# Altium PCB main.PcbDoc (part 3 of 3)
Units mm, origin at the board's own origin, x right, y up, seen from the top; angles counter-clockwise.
Board outline 326.29 x 232.51 mm, 2 copper layers (TopLayer, BottomLayer); 87 components, 134 nets, 466 pads, 108 vias.
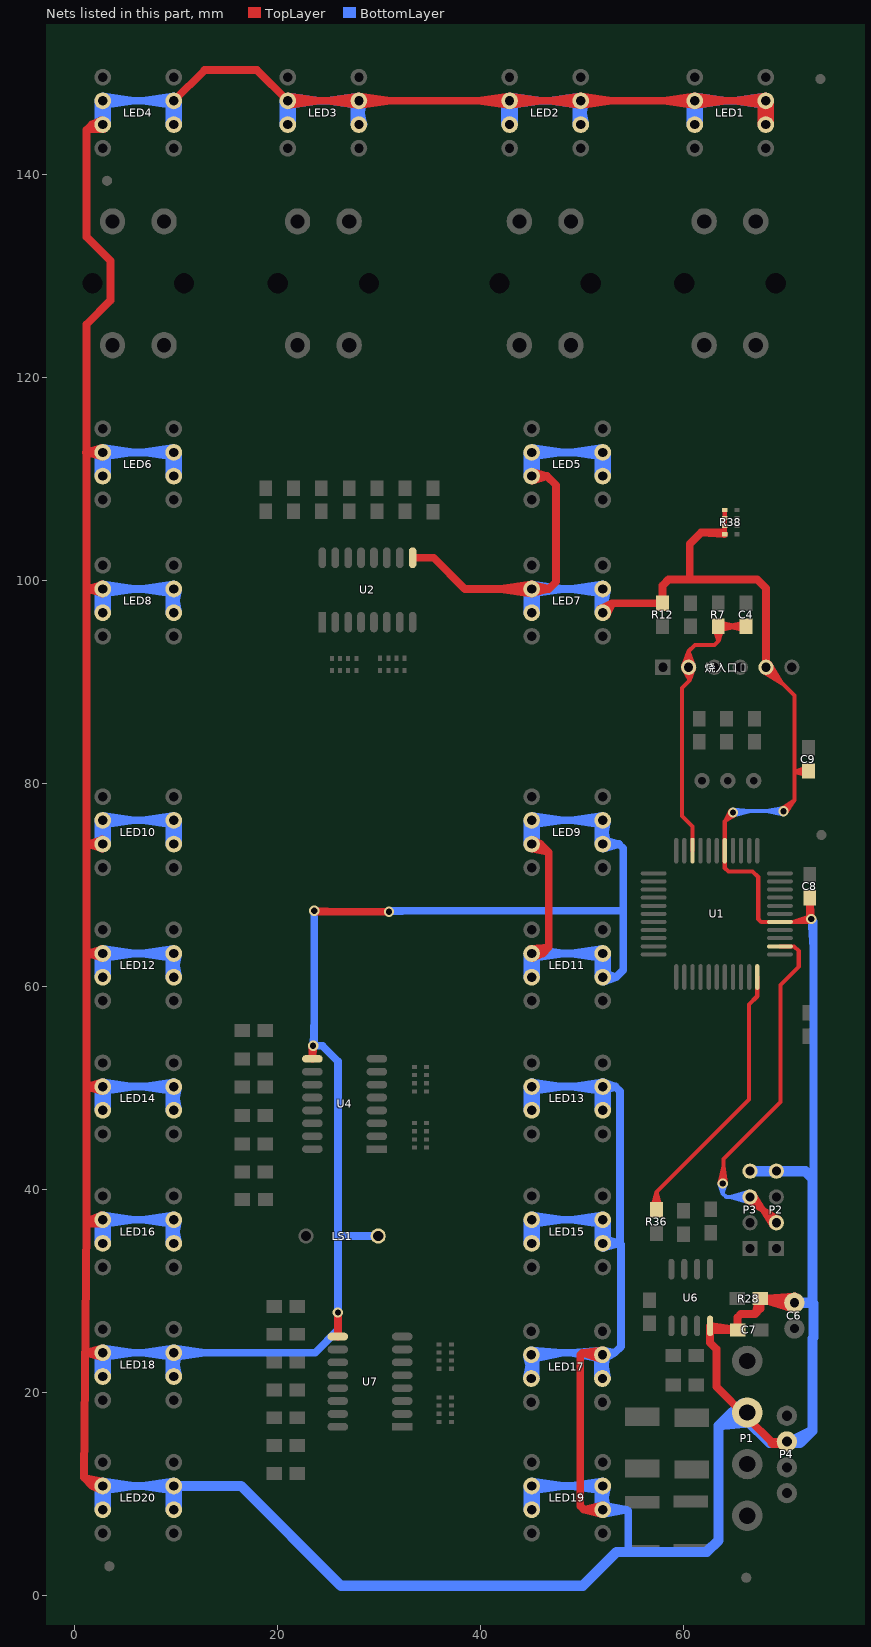
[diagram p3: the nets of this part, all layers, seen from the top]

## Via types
v1: diameter 1.016, hole 0.61, TopLayer to BottomLayer, tented both sides, 108 vias

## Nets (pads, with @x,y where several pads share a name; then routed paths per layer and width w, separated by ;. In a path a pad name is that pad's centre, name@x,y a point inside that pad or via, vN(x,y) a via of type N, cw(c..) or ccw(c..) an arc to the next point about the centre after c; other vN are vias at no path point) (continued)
TX: P2.2 P3.3 U1.35 | length 61.7
  TopLayer w0.406: v1@63.553,40.629 63.93,42.319 ; v1@64.16,40.603 63.93,42.319 ; P3.3@66.211,38.838 68.16,37.656 P3.3@66.978,39.606 ; P3.3@66.548,39.268 69.088,36.728 P2.2@69.139,36.728 67.508,38.308 ; P2.2@68.714,36.384 67.508,38.308 ; P2.2@69.469,37.164 67.508,38.308 ; U1.35@69.497,63.95 70.89,63.95 ; 63.93,42.319 v1(63.856,40.589) 63.93,40.515 63.93,43.004 69.545,48.619 69.545,60.151 71.351,61.957 71.351,63.488 70.89,63.95 ; 70.89,63.95 70.564,63.95 70.89,63.95
  BottomLayer w0.406: v1@63.555,40.541 63.856,39.624 ; v1@64.157,40.541 63.856,39.624 ; P3.3@66.472,38.727 64.579,39.268 ; P3.3@66.472,39.81 64.579,39.268 ; 63.856,39.624 v1(63.856,40.589) 63.856,39.624 ; 63.856,39.624 64.211,39.268 P3.3@66.548,39.268 64.579,39.268
TX2: R36.2 U1.33 | length 32.8
  TopLayer w0.406: R36.2@56.917,38.177 57.345,39.76 ; R36.2@57.345,37.993 57.345,39.76 ; R36.2@57.345,38.12 57.345,39.76 ; R36.2@57.773,38.177 57.345,39.76 ; U1.33@67.262,59.86 67.262,59.036 ; U1.33@67.262,60.927 67.262,59.036 ; 57.345,39.76 66.449,48.864 66.449,58.224 67.262,59.036
VCC: C6.1 C7.1 C8.1 C9.1 LED1.A LED2.A LED3.A LED4.A LED5.A LED6.A LED7.A LED8.A LED9.A LED10.A LED11.A LED12.A LED13.A LED14.A LED15.A LED16.A LED17.A LED18.A LED19.A LED20.A LS1.1 P1.2 P2.4 P3.4 P4.2 R12.2 R28.1 R38.1 R38.2 R38.3 R38.4 U1.5 U1.38 U2.9 U4.9 U6.8 U7.9 烧入口1.5 | length 2560.3
  TopLayer w0.406: U1.5@64.062,72.306 64.062,71.676 ; U1.5@64.062,74.44 64.062,75.862 ; v1@64.628,77.316 64.062,76.254 ; v1@65.073,76.907 64.062,76.254 ; 烧入口1.5@67.785,91.01 69.735,89.828 烧入口1.5@68.553,91.777 ; 烧入口1.5@68.123,91.44 70.917,88.646 70.917,81.125 ; U1.38@68.43,66.363 67.648,66.363 ; v1@69.652,77.498 70.917,78.334 ; v1(69.845,77.262) 70.917,78.334 ; v1@70.081,77.069 70.917,78.334 ; U1.38@70.564,66.363 71.986,66.363 ; C9.1@72.195,81.641 70.917,81.125 ; C9.1@72.254,80.79 70.917,81.125 ; v1@72.396,66.881 71.986,66.363 ; v1@72.512,66.938 70.817,66.363 ; v1@72.515,66.938 U1.38@70.76,66.363 ; v1@72.606,66.338 U1.38@70.76,66.363 ; v1@72.607,66.338 70.817,66.363 ; v1@72.647,66.343 71.986,66.363 ; R38.3@64.059,105.334 R38.2@64.059,106.134 ; R38.3@64.059,105.334 R38.4@64.059,104.534 R38.3@64.059,105.334 ; R38.3@64.059,105.334 R38.2@64.059,106.134 ; R38.2@64.059,106.134 R38.1@64.059,106.934 R38.2@64.059,106.134 ; 64.062,71.676 U1.5@64.062,73.373 64.062,76.254 ; 64.062,71.676 64.414,71.323 66.802,71.323 67.361,70.764 67.361,66.65 67.648,66.363 ; 64.062,76.254 64.922,77.114 64.897,77.14 v1(64.876,77.14) 64.062,76.254 ; 67.648,66.363 U1.38@69.497,66.363 72.306,66.363 v1(72.585,66.642) ; U1.38@70.76,66.363 v1(72.585,66.642) ; 70.817,66.363 v1(72.585,66.642) ; 70.917,78.334 70.917,81.125 ; 70.917,81.125 72.197,81.125 C9.1@72.292,81.22 70.917,81.125 ; 71.986,66.363 v1(72.585,66.642)
  TopLayer w0.762: 1.151,112.597 1.212,112.597 ; 1.174,50.137 1.212,50.137 ; 1.174,63.247 1.212,63.247 ; LED14.A@2.505,50.137 1.212,50.137 ; LED12.A@2.505,63.247 1.212,63.247 ; LED20.A@2.573,10.424 0.965,11.633 ; LED4.A@2.606,145.284 1.212,144.366 ; LED16.A@2.631,37.438 1.212,36.619 ; LED10.A@2.703,74.023 1.372,74.023 ; LED6.A@2.703,112.597 1.212,112.597 ; LED10.A@2.73,73.584 1.372,74.023 ; LED10.A@2.73,74.462 1.372,74.023 ; LED8.A@2.736,98.707 1.248,99.147 ; LED8.A@2.736,99.587 1.248,99.147 ; LED14.A@2.737,49.697 1.212,50.137 ; LED14.A@2.737,50.577 1.212,50.137 ; LED12.A@2.737,62.807 1.212,63.247 ; LED12.A@2.737,63.687 1.212,63.247 ; LED6.A@2.737,112.157 1.212,112.597 ; LED6.A@2.737,113.037 1.212,112.597 ; LED18.A@2.74,23.476 1.128,23.917 ; LED18.A@2.74,24.357 1.128,23.917 ; LED14.A@2.799,50.137 1.212,50.137 ; LED12.A@2.799,63.247 1.212,63.247 ; LED10.A@2.799,74.023 1.372,74.023 ; LED6.A@2.799,112.597 1.212,112.597 ; LED16.A@2.85,36.585 1.212,36.619 ; LED4.A@2.879,144.446 1.212,144.366 ; LED20.A@2.936,11.23 0.965,11.633 ; LED4.A@9.799,147.217 12.833,150.25 17.996,150.25 LED3.A@21.029,147.217 LED3.A@28.029,147.217 ; LED3.A@21.061,146.773 24.141,147.217 LED3.A@21.061,147.66 ; 26.427,67.361 v1(23.622,67.462) 23.724,67.361 v1(30.988,67.361) 28.194,67.361 ; LED3.A@27.997,146.773 24.918,147.217 ; LED3.A@27.997,147.66 24.918,147.217 ; LED3.A@28.061,146.773 31.141,147.217 LED3.A@28.061,147.66 ; U2.9@33.319,102.225 35.392,102.225 38.471,99.147 LED7.A@45.039,99.147 ; LED2.A@42.837,146.773 39.758,147.217 ; LED2.A@42.837,147.66 39.758,147.217 ; LED2.A@42.901,146.773 45.981,147.217 LED2.A@42.901,147.66 ; LED9.A@44.894,73.603 46.736,73.203 ; LED11.A@44.942,63.68 46.736,63.856 ; LED7.A@45.007,98.703 41.928,99.147 ; LED7.A@45.007,99.59 41.928,99.147 ; LED5.A@45.039,110.263 46.556,110.263 ; LED7.A@45.098,98.706 46.721,99.147 ; LED7.A@45.098,99.587 46.721,99.147 ; LED5.A@45.104,109.824 46.556,110.263 ; LED5.A@45.104,110.703 46.556,110.263 ; LED11.A@45.24,62.85 46.736,63.856 ; LED9.A@45.279,74.398 46.736,73.203 ; LED2.A@49.837,146.773 46.758,147.217 ; LED2.A@49.837,147.66 46.758,147.217 ; LED2.A@49.901,146.773 52.981,147.217 LED2.A@49.901,147.66 ; LED7.A@51.782,97.176 52.979,97.753 ; LED17.A@51.922,23.287 50.028,23.917 ; LED19.A@51.985,8.032 50.201,8.473 ; LED19.A@51.985,8.915 50.201,8.473 ; LED17.A@52.008,24.166 50.028,23.917 ; LED17.A@52.014,23.722 50.028,23.917 ; LED19.A@52.039,8.473 50.201,8.473 ; LED17.A@52.039,23.917 50.028,23.917 ; LED7.A@52.039,96.813 52.979,97.753 ; LED7.A@52.402,96.556 52.979,97.753 ; 55.015,97.753 R12.2@57.936,97.753 ; R12.2@57.936,97.88 57.936,99.491 ; LED1.A@61.067,146.773 57.988,147.217 LED1.A@61.067,147.66 ; LED1.A@61.131,146.773 64.211,147.217 LED1.A@61.131,147.66 ; U6.8@62.611,25.857 62.611,24.919 ; R28.1@67.442,29.253 67.056,27.737 ; LED1.A@67.657,147.174 LED1.A@68.099,144.883 ; LED1.A@67.657,147.259 LED1.A@67.657,144.926 ; LED1.A@67.673,147.091 LED1.A@68.542,144.926 ; LED1.A@68.067,146.773 64.988,147.217 LED1.A@68.067,147.66 ; 烧入口1.5@68.123,91.44 68.123,99.212 67.259,100.076 60.604,100.076 ; LED1.A@68.526,147.091 LED1.A@67.657,144.926 ; LED1.A@68.542,147.174 LED1.A@68.099,144.883 ; LED1.A@68.542,147.259 LED1.A@68.542,144.926 ; 68.775,15.037 66.275,17.537 63.246,20.566 63.246,24.284 62.611,24.919 ; C6.1@70.783,28.25 R28.1@67.696,29.253 ; C6.1@70.787,28.249 R28.1@67.569,29.253 ; 0.965,11.633 1.792,10.807 ; 0.965,11.633 1.212,36.619 ; 0.965,11.633 LED20.A@2.799,10.807 ; 1.128,23.917 LED18.A@2.799,23.917 1.128,23.917 ; 1.212,36.619 1.619,37.027 ; 1.212,36.619 1.212,50.137 ; 1.212,36.619 LED16.A@2.799,37.027 ; 1.212,50.137 1.212,63.247 ; 1.212,63.247 1.212,112.597 ; 1.212,112.597 1.212,125.214 3.561,127.564 3.561,131.465 1.212,133.815 1.212,144.366 ; 1.212,144.366 1.729,144.883 ; 1.212,144.366 LED4.A@2.799,144.883 ; 1.248,99.147 LED8.A@2.799,99.147 1.248,99.147 ; 1.619,37.027 LED16.A@2.799,37.027 ; 1.619,37.027 2.715,36.59 1.619,37.027 ; 1.619,37.027 2.715,37.463 1.619,37.027 ; 1.619,37.027 LED16.A@2.799,37.027 ; 1.619,37.027 LED16.A@2.799,37.027 ; 1.729,144.883 LED4.A@2.799,144.883 ; 1.729,144.883 2.707,144.449 1.729,144.883 ; 1.729,144.883 2.707,145.318 1.729,144.883 ; 1.729,144.883 LED4.A@2.799,144.883 ; 1.729,144.883 LED4.A@2.799,144.883 ; 1.792,10.807 LED20.A@2.799,10.807 ; 1.792,10.807 2.701,10.373 1.792,10.807 ; 1.792,10.807 2.701,11.24 1.792,10.807 ; 1.792,10.807 LED20.A@2.799,10.807 ; 1.792,10.807 LED20.A@2.799,10.807 ; 24.918,147.217 LED3.A@28.029,147.217 ; v1(25.959,27.889) 25.959,25.53 v1(25.959,27.889) ; v1(25.959,27.889) U7.9@25.949,25.52 v1(25.959,27.889) ; LED3.A@28.029,147.217 LED2.A@42.869,147.217 ; 39.758,147.217 LED2.A@42.869,147.217 ; 41.928,99.147 LED7.A@45.039,99.147 ; LED2.A@42.869,147.217 LED2.A@49.869,147.217 ; LED11.A@45.039,63.247 46.127,63.247 ; LED11.A@45.039,63.247 46.736,63.856 ; LED11.A@45.039,63.247 46.127,63.247 ; LED9.A@45.039,74.023 45.915,74.023 ; LED9.A@45.039,74.023 46.736,73.203 ; LED9.A@45.039,74.023 45.915,74.023 ; LED7.A@45.039,99.147 46.721,99.147 ; 45.915,74.023 46.736,73.203 ; 45.915,74.023 45.152,74.453 45.915,74.023 ; 45.915,74.023 45.152,73.593 45.915,74.023 ; 46.127,63.247 46.736,63.856 ; 46.127,63.247 45.13,63.682 46.127,63.247 ; 46.127,63.247 45.13,62.812 46.127,63.247 ; 46.556,110.263 47.447,109.372 47.447,99.873 46.721,99.147 ; 46.736,63.856 46.736,73.203 ; 46.758,147.217 LED2.A@49.869,147.217 ; LED2.A@49.869,147.217 LED1.A@61.099,147.217 LED1.A@68.099,147.217 ; 50.028,23.917 49.835,23.724 49.835,8.839 50.201,8.473 ; 52.979,97.753 R12.2@57.936,97.753 ; R12.2@57.936,97.753 57.936,99.491 ; 57.936,99.491 58.522,100.076 60.604,100.076 ; 60.604,100.076 60.604,103.581 61.722,104.699 ; 61.722,104.699 63.754,104.699 64.009,104.534 61.722,104.699 ; 62.611,24.919 U6.8@62.611,26.568 ; U6.8@62.611,26.568 63.01,26.17 ; U6.8@62.611,26.568 C7.1@65.324,26.17 ; U6.8@62.611,26.568 63.01,26.17 ; U6.8@62.611,26.568 65.197,26.17 63.01,26.17 ; U6.8@62.611,26.568 63.01,26.17 ; 63.01,26.17 C7.1@65.324,26.17 ; C7.1@65.324,26.17 65.324,27.427 65.634,27.737 67.056,27.737 ; 67.056,27.737 67.569,28.25 ; 67.569,28.25 R28.1@67.569,29.253 ; 67.569,28.25 R28.1@67.569,29.253 ; 67.569,28.25 R28.1@67.569,29.253 ; R28.1@67.569,29.253 C6.1@70.518,29.253 ; R28.1@67.569,29.253 70.933,29.473 R28.1@67.696,29.253 ; R28.1@67.569,29.253 C6.1@70.917,28.854 ; LED1.A@67.657,144.926 LED1.A@68.099,147.217 ; R28.1@67.696,29.253 C6.1@70.518,29.253 ; R28.1@67.696,29.253 C6.1@70.917,28.854 ; LED1.A@68.099,144.883 LED1.A@68.099,147.217 ; LED1.A@68.099,147.217 LED1.A@68.542,144.926 ; C6.1@70.518,29.253 C6.1@70.917,28.854 ; v1@72.433,66.794 C8.1@72.433,68.727 v1(72.585,66.642) ; v1@72.433,66.794 v1(72.585,66.642) ; v1@72.433,66.794 72.433,68.6 v1(72.585,66.642) ; U4.9@23.449,52.87 23.449,54.082 v1(23.52,54.153) U4.9@23.449,52.87
  TopLayer w1.016: P1.2@66.275,17.537 P1.2@66.275,18.04 ; 68.775,15.037 70.256,15.037 68.775,15.037
  BottomLayer w0.406: v1@64.882,77.445 66.615,77.262 ; v1@64.924,76.839 66.615,77.262 ; v1@69.818,76.958 68.118,77.262 ; v1@69.818,77.566 68.118,77.262 ; 66.615,77.262 v1(64.876,77.14) 64.876,77.262 v1(69.845,77.262) 68.118,77.262
  BottomLayer w0.762: LED20.A@2.357,10.764 LED20.A@2.799,8.473 ; LED20.A@2.357,10.849 LED20.A@2.357,8.516 ; LED18.A@2.357,23.874 LED18.A@2.799,21.583 ; LED18.A@2.357,23.959 LED18.A@2.357,21.626 ; LED16.A@2.357,36.984 LED16.A@2.799,34.693 ; LED16.A@2.357,37.069 LED16.A@2.357,34.736 ; LED14.A@2.357,50.094 LED14.A@2.799,47.803 ; LED14.A@2.357,50.179 LED14.A@2.357,47.846 ; LED12.A@2.357,63.204 LED12.A@2.799,60.913 ; LED12.A@2.357,63.289 LED12.A@2.357,60.956 ; LED10.A@2.357,76.314 LED10.A@2.799,74.023 ; LED10.A@2.357,76.399 LED10.A@2.357,74.066 ; LED8.A@2.357,99.104 LED8.A@2.799,96.813 ; LED8.A@2.357,99.189 LED8.A@2.357,96.856 ; LED6.A@2.357,112.554 LED6.A@2.799,110.263 ; LED6.A@2.357,112.639 LED6.A@2.357,110.306 ; LED4.A@2.357,147.174 LED4.A@2.799,144.883 ; LED4.A@2.357,147.259 LED4.A@2.357,144.926 ; LED20.A@2.373,10.681 LED20.A@3.242,8.516 ; LED18.A@2.373,23.791 LED18.A@3.242,21.626 ; LED16.A@2.373,36.901 LED16.A@3.242,34.736 ; LED14.A@2.373,50.011 LED14.A@3.242,47.846 ; LED12.A@2.373,63.121 LED12.A@3.242,60.956 ; LED10.A@2.373,76.231 LED10.A@3.242,74.066 ; LED8.A@2.373,99.021 LED8.A@3.242,96.856 ; LED6.A@2.373,112.471 LED6.A@3.242,110.306 ; LED4.A@2.373,147.091 LED4.A@3.242,144.926 ; LED20.A@2.601,10.807 LED20.A@2.799,10.807 ; LED18.A@2.601,23.917 LED18.A@2.799,23.917 ; LED16.A@2.601,37.027 LED16.A@2.799,37.027 ; LED14.A@2.601,50.137 LED14.A@2.799,50.137 ; LED12.A@2.601,63.247 LED12.A@2.799,63.247 ; LED10.A@2.601,76.357 LED10.A@2.799,76.357 ; LED8.A@2.601,99.147 LED8.A@2.799,99.147 ; LED6.A@2.601,112.597 LED6.A@2.799,112.597 ; LED4.A@2.601,147.217 LED4.A@2.799,147.217 ; LED20.A@2.831,10.363 5.911,10.807 LED20.A@2.831,11.25 ; LED18.A@2.831,23.473 5.911,23.917 LED18.A@2.831,24.36 ; LED16.A@2.831,36.583 5.911,37.027 LED16.A@2.831,37.47 ; LED14.A@2.831,49.693 5.911,50.137 LED14.A@2.831,50.58 ; LED12.A@2.831,62.803 5.911,63.247 LED12.A@2.831,63.69 ; LED10.A@2.831,75.913 5.911,76.357 LED10.A@2.831,76.8 ; LED8.A@2.831,98.703 5.911,99.147 LED8.A@2.831,99.59 ; LED6.A@2.831,112.153 5.911,112.597 LED6.A@2.831,113.04 ; LED4.A@2.831,146.773 5.911,147.217 LED4.A@2.831,147.66 ; LED20.A@3.226,10.681 LED20.A@2.357,8.516 ; LED18.A@3.226,23.791 LED18.A@2.357,21.626 ; LED16.A@3.226,36.901 LED16.A@2.357,34.736 ; LED14.A@3.226,50.011 LED14.A@2.357,47.846 ; LED12.A@3.226,63.121 LED12.A@2.357,60.956 ; LED10.A@3.226,76.231 LED10.A@2.357,74.066 ; LED8.A@3.226,99.021 LED8.A@2.357,96.856 ; LED6.A@3.226,112.471 LED6.A@2.357,110.306 ; LED4.A@3.226,147.091 LED4.A@2.357,144.926 ; LED20.A@3.242,10.764 LED20.A@2.799,8.473 ; LED20.A@3.242,10.849 LED20.A@3.242,8.516 ; LED18.A@3.242,23.874 LED18.A@2.799,21.583 ; LED18.A@3.242,23.959 LED18.A@3.242,21.626 ; LED16.A@3.242,36.984 LED16.A@2.799,34.693 ; LED16.A@3.242,37.069 LED16.A@3.242,34.736 ; LED14.A@3.242,50.094 LED14.A@2.799,47.803 ; LED14.A@3.242,50.179 LED14.A@3.242,47.846 ; LED12.A@3.242,63.204 LED12.A@2.799,60.913 ; LED12.A@3.242,63.289 LED12.A@3.242,60.956 ; LED10.A@3.242,76.314 LED10.A@2.799,74.023 ; LED10.A@3.242,76.399 LED10.A@3.242,74.066 ; LED8.A@3.242,99.104 LED8.A@2.799,96.813 ; LED8.A@3.242,99.189 LED8.A@3.242,96.856 ; LED6.A@3.242,112.554 LED6.A@2.799,110.263 ; LED6.A@3.242,112.639 LED6.A@3.242,110.306 ; LED4.A@3.242,147.174 LED4.A@2.799,144.883 ; LED4.A@3.242,147.259 LED4.A@3.242,144.926 ; LED20.A@9.357,8.431 LED20.A@9.357,10.764 ; LED18.A@9.357,21.541 LED18.A@9.357,23.874 ; LED16.A@9.357,34.651 LED16.A@9.357,36.984 ; LED14.A@9.357,47.761 LED14.A@9.357,50.094 ; LED12.A@9.357,60.871 LED12.A@9.357,63.204 ; LED10.A@9.357,73.981 LED10.A@9.357,76.314 ; LED8.A@9.357,96.771 LED8.A@9.357,99.104 ; LED6.A@9.357,110.221 LED6.A@9.357,112.554 ; LED4.A@9.357,144.841 LED4.A@9.357,147.174 ; LED20.A@9.373,8.599 LED20.A@10.242,10.764 ; LED10.A@9.373,74.149 LED10.A@10.242,76.314 ; LED6.A@9.373,110.389 LED6.A@10.242,112.554 ; LED4.A@9.373,145.009 LED4.A@10.242,147.174 ; LED20.A@9.601,10.807 LED20.A@2.799,10.807 ; LED18.A@9.601,23.917 LED18.A@2.799,23.917 ; LED16.A@9.601,37.027 LED16.A@2.799,37.027 ; LED14.A@9.601,50.137 LED14.A@2.799,50.137 ; LED12.A@9.601,63.247 LED12.A@2.799,63.247 ; LED10.A@9.601,76.357 LED10.A@2.799,76.357 ; LED8.A@9.601,99.147 LED8.A@2.799,99.147 ; LED6.A@9.601,112.597 LED6.A@2.799,112.597 ; LED4.A@9.601,147.217 LED4.A@2.799,147.217 ; LED20.A@9.767,10.363 6.688,10.807 ; LED20.A@9.767,11.25 6.688,10.807 ; LED18.A@9.767,23.473 6.688,23.917 ; LED18.A@9.767,24.36 6.688,23.917 ; LED16.A@9.767,36.583 6.688,37.027 ; LED16.A@9.767,37.47 6.688,37.027 ; LED14.A@9.767,49.693 6.688,50.137 ; LED14.A@9.767,50.58 6.688,50.137 ; LED12.A@9.767,62.803 6.688,63.247 ; LED12.A@9.767,63.69 6.688,63.247 ; LED10.A@9.767,75.913 6.688,76.357 ; LED10.A@9.767,76.8 6.688,76.357 ; LED8.A@9.767,98.703 6.688,99.147 ; LED8.A@9.767,99.59 6.688,99.147 ; LED6.A@9.767,112.153 6.688,112.597 ; LED6.A@9.767,113.04 6.688,112.597 ; LED4.A@9.767,146.773 6.688,147.217 ; LED4.A@9.767,147.66 6.688,147.217 ; LED18.A@9.831,23.473 12.911,23.917 LED18.A@9.831,24.36 ; LED20.A@10.226,8.599 LED20.A@9.357,10.764 ; LED18.A@10.226,21.709 LED18.A@9.357,23.874 ; LED16.A@10.226,34.819 LED16.A@9.357,36.984 ; LED14.A@10.226,47.929 LED14.A@9.357,50.094 ; LED12.A@10.226,61.039 LED12.A@9.357,63.204 ; LED10.A@10.226,74.149 LED10.A@9.357,76.314 ; LED8.A@10.226,96.939 LED8.A@9.357,99.104 ; LED6.A@10.226,110.389 LED6.A@9.357,112.554 ; LED4.A@10.226,145.009 LED4.A@9.357,147.174 ; LED20.A@10.242,8.431 LED20.A@10.242,10.764 ; LED18.A@10.242,23.874 LED18.A@9.799,21.583 ; LED16.A@10.242,36.984 LED16.A@9.799,34.693 ; LED14.A@10.242,50.094 LED14.A@9.799,47.803 ; LED12.A@10.242,63.204 LED12.A@9.799,60.913 ; LED10.A@10.242,73.981 LED10.A@10.242,76.314 ; LED8.A@10.242,99.104 LED8.A@9.799,96.813 ; LED6.A@10.242,110.221 LED6.A@10.242,112.554 ; LED4.A@10.242,144.841 LED4.A@10.242,147.174 ; LED3.A@20.587,144.841 LED3.A@20.587,147.174 ; LED3.A@20.603,145.009 LED3.A@21.472,147.174 ; LED3.A@20.831,147.217 LED3.A@21.029,147.217 ; LED3.A@21.061,146.773 24.141,147.217 LED3.A@21.061,147.66 ; LED3.A@21.456,145.009 LED3.A@20.587,147.174 ; LED3.A@21.472,144.841 LED3.A@21.472,147.174 ; 23.622,56.958 v1(23.52,54.153) ; 23.622,64.668 v1(23.622,67.462) 23.622,54.254 v1(23.52,54.153) ; LED3.A@27.587,147.174 LED3.A@28.029,144.883 ; LED3.A@27.587,147.259 LED3.A@27.587,144.926 ; LED3.A@27.831,147.217 LED3.A@21.029,147.217 ; LED3.A@27.997,146.773 24.918,147.217 ; LED3.A@27.997,147.66 24.918,147.217 ; LED3.A@28.456,147.091 LED3.A@27.587,144.926 ; LED3.A@28.472,144.926 LED3.A@28.029,147.217 ; LED3.A@28.472,147.174 LED3.A@28.029,144.883 ; LS1.1@29.928,35.416 25.959,35.416 ; 33.794,67.462 v1(30.988,67.361) 31.09,67.462 54.051,67.462 ; LED2.A@42.427,147.174 LED2.A@42.869,144.883 ; LED2.A@42.427,147.259 LED2.A@42.427,144.926 ; LED2.A@42.443,147.091 LED2.A@43.312,144.926 ; LED2.A@42.671,147.217 LED2.A@42.869,147.217 ; LED2.A@42.901,146.773 45.981,147.217 LED2.A@42.901,147.66 ; LED2.A@43.296,147.091 LED2.A@42.427,144.926 ; LED2.A@43.312,147.174 LED2.A@42.869,144.883 ; LED2.A@43.312,147.259 LED2.A@43.312,144.926 ; LED17.A@44.572,23.67 LED17.A@45.039,21.583 ; LED17.A@44.588,21.514 LED17.A@45.457,23.681 ; LED19.A@44.597,8.431 LED19.A@44.597,10.764 ; LED15.A@44.597,34.651 LED15.A@44.597,36.984 ; LED13.A@44.597,47.761 LED13.A@44.597,50.094 ; LED11.A@44.597,60.871 LED11.A@44.597,63.204 ; LED9.A@44.597,73.981 LED9.A@44.597,76.314 ; LED7.A@44.597,96.771 LED7.A@44.597,99.104 ; LED5.A@44.597,110.221 LED5.A@44.597,112.554 ; LED19.A@44.613,8.599 LED19.A@45.482,10.764 ; LED15.A@44.613,34.819 LED15.A@45.482,36.984 ; LED13.A@44.613,47.929 LED13.A@45.482,50.094 ; LED11.A@44.613,61.039 LED11.A@45.482,63.204 ; LED9.A@44.613,74.149 LED9.A@45.482,76.314 ; LED7.A@44.613,96.939 LED7.A@45.482,99.104 ; LED5.A@44.613,110.389 LED5.A@45.482,112.554 ; LED19.A@44.841,10.807 LED19.A@45.039,10.807 ; LED17.A@44.841,23.917 LED17.A@45.039,23.917 ; LED15.A@44.841,37.027 LED15.A@45.039,37.027 ; LED13.A@44.841,50.137 LED13.A@45.039,50.137 ; LED11.A@44.841,63.247 LED11.A@45.039,63.247 ; LED9.A@44.841,76.357 LED9.A@45.039,76.357 ; LED7.A@44.841,99.147 LED7.A@45.039,99.147 ; LED5.A@44.841,112.597 LED5.A@45.039,112.597 ; LED17.A@45.018,24.166 48.144,23.917 ; LED19.A@45.071,10.363 48.151,10.807 LED19.A@45.071,11.25 ; LED15.A@45.071,36.583 48.151,37.027 LED15.A@45.071,37.47 ; LED13.A@45.071,49.693 48.151,50.137 LED13.A@45.071,50.58 ; LED11.A@45.071,62.803 48.151,63.247 LED11.A@45.071,63.69 ; LED9.A@45.071,75.913 48.151,76.357 LED9.A@45.071,76.8 ; LED7.A@45.071,98.703 48.151,99.147 LED7.A@45.071,99.59 ; LED5.A@45.071,112.153 48.151,112.597 LED5.A@45.071,113.04 ; LED17.A@45.073,23.281 48.144,23.917 ; LED17.A@45.456,21.346 LED17.A@45.457,23.681 ; LED17.A@45.456,21.431 LED17.A@45.014,23.722 ; LED17.A@45.457,21.423 LED17.A@45.039,23.917 ; LED19.A@45.466,8.599 LED19.A@44.597,10.764 ; LED15.A@45.466,34.819 LED15.A@44.597,36.984 ; LED13.A@45.466,47.929 LED13.A@44.597,50.094 ; LED11.A@45.466,61.039 LED11.A@44.597,63.204 ; LED9.A@45.466,74.149 LED9.A@44.597,76.314 ; LED7.A@45.466,96.939 LED7.A@44.597,99.104 ; LED5.A@45.466,110.389 LED5.A@44.597,112.554 ; LED19.A@45.482,8.431 LED19.A@45.482,10.764 ; LED15.A@45.482,34.651 LED15.A@45.482,36.984 ; LED13.A@45.482,47.761 LED13.A@45.482,50.094 ; LED11.A@45.482,60.871 LED11.A@45.482,63.204 ; LED9.A@45.482,73.981 LED9.A@45.482,76.314 ; LED7.A@45.482,96.771 LED7.A@45.482,99.104 ; LED5.A@45.482,110.221 LED5.A@45.482,112.554 ; LED2.A@49.427,144.841 LED2.A@49.427,147.174 ; LED2.A@49.671,147.217 LED2.A@42.869,147.217 ; LED2.A@49.837,146.773 46.758,147.217 ; LED2.A@49.837,147.66 46.758,147.217 ; LED2.A@50.296,145.009 LED2.A@49.427,147.174 ; LED2.A@50.312,147.174 LED2.A@49.869,144.883 ; LED17.A@51.572,23.68 LED17.A@52.014,21.389 ; LED17.A@51.572,23.764 LED17.A@51.572,21.432 ; LED17.A@51.573,23.67 LED17.A@52.039,21.583 ; LED19.A@51.597,10.764 LED19.A@52.039,8.473 ; LED19.A@51.597,10.849 LED19.A@51.597,8.516 ; LED15.A@51.597,36.984 LED15.A@52.039,34.693 ; LED15.A@51.597,37.069 LED15.A@51.597,34.736 ; LED13.A@51.597,50.094 LED13.A@52.039,47.803 ; LED13.A@51.597,50.179 LED13.A@51.597,47.846 ; LED11.A@51.597,63.204 LED11.A@52.039,60.913 ; LED11.A@51.597,63.289 LED11.A@51.597,60.956 ; LED9.A@51.597,76.314 LED9.A@52.039,74.023 ; LED9.A@51.597,76.399 LED9.A@51.597,74.066 ; LED7.A@51.597,99.104 LED7.A@52.039,96.813 ; LED7.A@51.597,99.189 LED7.A@51.597,96.856 ; LED5.A@51.597,112.554 LED5.A@52.039,110.263 ; LED5.A@51.597,112.639 LED5.A@51.597,110.306 ; LED15.A@51.613,36.901 LED15.A@52.482,34.736 ; LED13.A@51.613,50.011 LED13.A@52.482,47.846 ; LED11.A@51.613,63.121 LED11.A@52.482,60.956 ; LED5.A@51.613,112.471 LED5.A@52.482,110.306 ; LED19.A@51.841,10.807 LED19.A@45.039,10.807 ; LED17.A@51.841,23.917 LED17.A@45.039,23.917 ; LED15.A@51.841,37.027 LED15.A@45.039,37.027 ; LED13.A@51.841,50.137 LED13.A@45.039,50.137 ; LED11.A@51.841,63.247 LED11.A@45.039,63.247 ; LED9.A@51.841,76.357 LED9.A@45.039,76.357 ; LED7.A@51.841,99.147 LED7.A@45.039,99.147 ; LED5.A@51.841,112.597 LED5.A@45.039,112.597 ; LED17.A@51.955,23.281 48.88,23.917 ; LED19.A@52.007,10.363 48.928,10.807 ; LED19.A@52.007,11.25 48.928,10.807 ; LED15.A@52.007,36.583 48.928,37.027 ; LED15.A@52.007,37.47 48.928,37.027 ; LED13.A@52.007,49.693 48.928,50.137 ; LED13.A@52.007,50.58 48.928,50.137 ; LED11.A@52.007,62.803 48.928,63.247 ; LED11.A@52.007,63.69 48.928,63.247 ; LED9.A@52.007,75.913 48.928,76.357 ; LED9.A@52.007,76.8 48.928,76.357 ; LED7.A@52.007,98.703 48.928,99.147 ; LED7.A@52.007,99.59 48.928,99.147 ; LED5.A@52.007,112.153 48.928,112.597 ; LED5.A@52.007,113.04 48.928,112.597 ; LED17.A@52.01,24.166 48.88,23.917 ; LED17.A@52.024,24.166 53.228,23.917 ; LED19.A@52.081,8.031 54.417,8.473 ; LED19.A@52.081,8.916 54.417,8.473 ; LED15.A@52.097,34.253 53.745,34.693 ; LED15.A@52.097,35.134 53.745,34.693 ; LED9.A@52.101,73.583 53.637,74.023 ; LED9.A@52.101,74.464 53.637,74.023 ; LED11.A@52.115,60.475 53.344,60.913 ; LED11.A@52.115,61.351 53.344,60.913 ; LED13.A@52.118,49.699 53.292,50.137 ; LED13.A@52.118,50.574 53.292,50.137 ; LED17.A@52.163,23.303 53.228,23.917 ; LED17.A@52.44,23.596 LED17.A@51.572,21.432 ; LED17.A@52.456,23.68 LED17.A@52.014,21.389 ; LED17.A@52.457,23.681 LED17.A@52.039,21.583 ; LED17.A@52.457,21.423 LED17.A@52.039,23.917 ; LED19.A@52.466,10.681 LED19.A@51.597,8.516 ; LED15.A@52.466,36.901 LED15.A@51.597,34.736 ; LED13.A@52.466,50.011 LED13.A@51.597,47.846 ; LED11.A@52.466,63.121 LED11.A@51.597,60.956 ; LED9.A@52.466,76.231 LED9.A@51.597,74.066 ; LED7.A@52.466,99.021 LED7.A@51.597,96.856 ; LED5.A@52.466,112.471 LED5.A@51.597,110.306 ; LED19.A@52.482,8.516 LED19.A@52.039,10.807 ; LED19.A@52.482,10.764 LED19.A@52.039,8.473 ; LED15.A@52.482,36.984 LED15.A@52.039,34.693 ; LED15.A@52.482,37.069 LED15.A@52.482,34.736 ; LED13.A@52.482,50.094 LED13.A@52.039,47.803 ; LED13.A@52.482,50.179 LED13.A@52.482,47.846 ; LED11.A@52.482,63.204 LED11.A@52.039,60.913 ; LED11.A@52.482,63.289 LED11.A@52.482,60.956 ; LED9.A@52.482,74.066 LED9.A@52.039,76.357 ; LED9.A@52.482,76.314 LED9.A@52.039,74.023 ; LED7.A@52.482,96.856 LED7.A@52.039,99.147 ; LED7.A@52.482,99.104 LED7.A@52.039,96.813 ; LED5.A@52.482,112.554 LED5.A@52.039,110.263 ; LED5.A@52.482,112.639 LED5.A@52.482,110.306 ; 54.559,4.275 54.559,4.31 54.559,8.331 54.417,8.473 ; LED1.A@60.657,144.841 LED1.A@60.657,147.174 ; LED1.A@60.673,145.009 LED1.A@61.542,147.174 ; LED1.A@60.901,147.217 LED1.A@61.099,147.217 ; LED1.A@61.131,146.773 64.211,147.217 LED1.A@61.131,147.66 ; LED1.A@61.526,145.009 LED1.A@60.657,147.174 ; LED1.A@61.542,144.841 LED1.A@61.542,147.174 ; LED1.A@67.901,147.217 LED1.A@61.099,147.217 ; LED1.A@68.067,146.773 64.988,147.217 ; LED1.A@68.067,147.66 64.988,147.217 ; LED1.A@68.099,147.217 64.988,147.217 ; 72.806,40.377 72.806,66.421 v1(72.585,66.642) 72.806,63.776 ; LED20.A@2.357,8.516 LED20.A@2.799,10.807 ; LED20.A@2.357,8.516 LED20.A@2.799,10.807 ; LED18.A@2.357,21.626 LED18.A@2.799,23.917 ; LED18.A@2.357,21.626 LED18.A@2.799,23.917 ; LED16.A@2.357,34.736 LED16.A@2.799,37.027 ; LED16.A@2.357,34.736 LED16.A@2.799,37.027 ; LED14.A@2.357,47.846 LED14.A@2.799,50.137 ; LED14.A@2.357,47.846 LED14.A@2.799,50.137 ; LED12.A@2.357,60.956 LED12.A@2.799,63.247 ; LED12.A@2.357,60.956 LED12.A@2.799,63.247 ; LED10.A@2.357,74.066 LED10.A@2.799,76.357 ; LED10.A@2.357,74.066 LED10.A@2.799,76.357 ; LED8.A@2.357,96.856 LED8.A@2.799,99.147 ; LED8.A@2.357,96.856 LED8.A@2.799,99.147 ; LED6.A@2.357,110.306 LED6.A@2.799,112.597 ; LED6.A@2.357,110.306 LED6.A@2.799,112.597 ; LED4.A@2.357,144.926 LED4.A@2.799,147.217 ; LED4.A@2.357,144.926 LED4.A@2.799,147.217 ; LED20.A@2.799,8.473 LED20.A@2.799,10.807 ; LED20.A@2.799,8.473 LED20.A@2.799,10.807 ; LED20.A@2.799,10.807 LED20.A@3.242,8.516 ; LED18.A@2.799,21.583 LED18.A@2.799,23.917 ; LED18.A@2.799,21.583 LED18.A@2.799,23.917 ; LED18.A@2.799,23.917 LED18.A@3.242,21.626 ; LED16.A@2.799,34.693 LED16.A@2.799,37.027 ; LED16.A@2.799,34.693 LED16.A@2.799,37.027 ; LED16.A@2.799,37.027 LED16.A@3.242,34.736 ; LED14.A@2.799,47.803 LED14.A@2.799,50.137 ; LED14.A@2.799,47.803 LED14.A@2.799,50.137 ; LED14.A@2.799,50.137 LED14.A@3.242,47.846 ; LED12.A@2.799,60.913 LED12.A@2.799,63.247 ; LED12.A@2.799,60.913 LED12.A@2.799,63.247 ; LED12.A@2.799,63.247 LED12.A@3.242,60.956 ; LED10.A@2.799,74.023 LED10.A@2.799,76.357 ; LED10.A@2.799,74.023 LED10.A@2.799,76.357 ; LED10.A@2.799,76.357 LED10.A@3.242,74.066 ; LED8.A@2.799,96.813 LED8.A@2.799,99.147 ; LED8.A@2.799,96.813 LED8.A@2.799,99.147 ; LED8.A@2.799,99.147 LED8.A@3.242,96.856 ; LED6.A@2.799,110.263 LED6.A@2.799,112.597 ; LED6.A@2.799,110.263 LED6.A@2.799,112.597 ; LED6.A@2.799,112.597 LED6.A@3.242,110.306 ; LED4.A@2.799,144.883 LED4.A@2.799,147.217 ; LED4.A@2.799,144.883 LED4.A@2.799,147.217 ; LED4.A@2.799,147.217 LED4.A@3.242,144.926 ; 6.688,10.807 LED20.A@9.799,10.807 ; 6.688,23.917 LED18.A@9.799,23.917 ; 6.688,37.027 LED16.A@9.799,37.027 ; 6.688,50.137 LED14.A@9.799,50.137 ; 6.688,63.247 LED12.A@9.799,63.247 ; 6.688,76.357 LED10.A@9.799,76.357 ; 6.688,99.147 LED8.A@9.799,99.147 ; 6.688,112.597 LED6.A@9.799,112.597 ; 6.688,147.217 LED4.A@9.799,147.217 ; LED20.A@9.357,10.764 LED20.A@9.799,8.473 ; LED20.A@9.357,10.764 LED20.A@9.799,8.473 ; LED18.A@9.357,23.874 LED18.A@9.799,21.583 ; LED18.A@9.357,23.874 LED18.A@9.799,21.583 ; LED16.A@9.357,36.984 LED16.A@9.799,34.693 ; LED16.A@9.357,36.984 LED16.A@9.799,34.693 ; LED14.A@9.357,50.094 LED14.A@9.799,47.803 ; LED14.A@9.357,50.094 LED14.A@9.799,47.803 ; LED12.A@9.357,63.204 LED12.A@9.799,60.913 ; LED12.A@9.357,63.204 LED12.A@9.799,60.913 ; LED10.A@9.357,76.314 LED10.A@9.799,74.023 ; LED10.A@9.357,76.314 LED10.A@9.799,74.023 ; LED8.A@9.357,99.104 LED8.A@9.799,96.813 ; LED8.A@9.357,99.104 LED8.A@9.799,96.813 ; LED6.A@9.357,112.554 LED6.A@9.799,110.263 ; LED6.A@9.357,112.554 LED6.A@9.799,110.263 ; LED4.A@9.357,147.174 LED4.A@9.799,144.883 ; LED4.A@9.357,147.174 LED4.A@9.799,144.883 ; LED20.A@9.799,8.473 LED20.A@9.799,10.807 ; LED20.A@9.799,8.473 LED20.A@10.242,10.764 ; LED20.A@9.799,8.473 LED20.A@9.799,10.807 ; LED20.A@9.799,10.807 9.357,8.516 LED20.A@9.799,10.807 ; LED20.A@9.799,10.807 10.242,8.516 LED20.A@9.799,10.807 ; LED18.A@9.799,21.583 LED18.A@9.799,23.917 ; LED18.A@9.799,21.583 LED18.A@9.799,23.917 ; LED18.A@9.799,23.917 23.713,23.917 25.959,26.162 ; LED18.A@9.799,23.917 9.357,21.626 LED18.A@9.799,23.917 ; LED18.A@9.799,23.917 10.242,21.626 LED18.A@9.799,23.917 ; LED16.A@9.799,34.693 LED16.A@9.799,37.027 ; LED16.A@9.799,34.693 LED16.A@9.799,37.027 ; LED16.A@9.799,37.027 9.357,34.736 LED16.A@9.799,37.027 ; LED16.A@9.799,37.027 10.242,34.736 LED16.A@9.799,37.027 ; LED14.A@9.799,47.803 LED14.A@9.799,50.137 ; LED14.A@9.799,47.803 LED14.A@9.799,50.137 ; LED14.A@9.799,50.137 9.357,47.846 LED14.A@9.799,50.137 ; LED14.A@9.799,50.137 10.242,47.846 LED14.A@9.799,50.137 ; LED12.A@9.799,60.913 LED12.A@9.799,63.247 ; LED12.A@9.799,60.913 LED12.A@9.799,63.247 ; LED12.A@9.799,63.247 9.357,60.956 LED12.A@9.799,63.247 ; LED12.A@9.799,63.247 10.242,60.956 LED12.A@9.799,63.247 ; LED10.A@9.799,74.023 LED10.A@9.799,76.357 ; LED10.A@9.799,74.023 LED10.A@10.242,76.314 ; LED10.A@9.799,74.023 LED10.A@9.799,76.357 ; LED10.A@9.799,76.357 9.357,74.066 LED10.A@9.799,76.357 ; LED10.A@9.799,76.357 10.242,74.066 LED10.A@9.799,76.357 ; LED8.A@9.799,96.813 LED8.A@9.799,99.147 ; LED8.A@9.799,96.813 LED8.A@9.799,99.147 ; LED8.A@9.799,99.147 9.357,96.856 LED8.A@9.799,99.147 ; LED8.A@9.799,99.147 10.242,96.856 LED8.A@9.799,99.147 ; LED6.A@9.799,110.263 LED6.A@9.799,112.597 ; LED6.A@9.799,110.263 LED6.A@10.242,112.554 ; LED6.A@9.799,110.263 LED6.A@9.799,112.597 ; LED6.A@9.799,112.597 9.357,110.306 LED6.A@9.799,112.597 ; LED6.A@9.799,112.597 10.242,110.306 LED6.A@9.799,112.597 ; LED4.A@9.799,144.883 LED4.A@9.799,147.217 ; LED4.A@9.799,144.883 LED4.A@10.242,147.174 ; LED4.A@9.799,144.883 LED4.A@9.799,147.217 ; LED4.A@9.799,147.217 9.357,144.926 LED4.A@9.799,147.217 ; LED4.A@9.799,147.217 10.242,144.926 LED4.A@9.799,147.217 ; LED3.A@20.587,147.174 LED3.A@21.029,144.883 ; LED3.A@20.587,147.174 LED3.A@21.029,144.883 ; LED3.A@21.029,144.883 LED3.A@21.029,147.217 ; LED3.A@21.029,144.883 LED3.A@21.472,147.174 ; LED3.A@21.029,144.883 LED3.A@21.029,147.217 ; LED3.A@21.029,147.217 20.587,144.926 LED3.A@21.029,147.217 ; LED3.A@21.029,147.217 21.472,144.926 LED3.A@21.029,147.217 ; v1(23.52,54.153) 24.435,54.153 25.959,52.629 25.959,35.416 ; 24.918,147.217 LED3.A@28.029,147.217 ; 25.959,26.162 v1(25.959,27.889) ; 25.959,26.162 v1(25.959,27.889) ; v1(25.959,27.889) 25.959,35.416 ; LED3.A@27.587,144.926 LED3.A@28.029,147.217 ; LED3.A@27.587,144.926 LED3.A@28.029,147.217 ; LED3.A@28.029,144.883 LED3.A@28.029,147.217 ; LED3.A@28.029,144.883 LED3.A@28.029,147.217 ; LED2.A@42.427,144.926 LED2.A@42.869,147.217 ; LED2.A@42.427,144.926 LED2.A@42.869,147.217 ; LED2.A@42.869,144.883 LED2.A@42.869,147.217 ; LED2.A@42.869,144.883 LED2.A@42.869,147.217 ; LED2.A@42.869,147.217 LED2.A@43.312,144.926 ; LED19.A@44.597,10.764 LED19.A@45.039,8.473 ; LED19.A@44.597,10.764 LED19.A@45.039,8.473 ; LED15.A@44.597,36.984 LED15.A@45.039,34.693 ; LED15.A@44.597,36.984 LED15.A@45.039,34.693 ; LED13.A@44.597,50.094 LED13.A@45.039,47.803 ; LED13.A@44.597,50.094 LED13.A@45.039,47.803 ; LED11.A@44.597,63.204 LED11.A@45.039,60.913 ; LED11.A@44.597,63.204 LED11.A@45.039,60.913 ; LED9.A@44.597,76.314 LED9.A@45.039,74.023 ; LED9.A@44.597,76.314 LED9.A@45.039,74.023 ; LED7.A@44.597,99.104 LED7.A@45.039,96.813 ; LED7.A@44.597,99.104 LED7.A@45.039,96.813 ; LED5.A@44.597,112.554 LED5.A@45.039,110.263 ; LED5.A@44.597,112.554 LED5.A@45.039,110.263 ; LED17.A@45.014,21.389 LED17.A@45.039,23.917 ; LED17.A@45.014,21.389 LED17.A@45.457,23.681 ; LED17.A@45.014,21.389 LED17.A@45.014,23.722 ; LED17.A@45.014,23.722 LED17.A@45.039,21.583 ; LED17.A@45.014,23.722 48.144,23.917 ; LED17.A@45.014,23.722 44.572,21.431 LED17.A@45.039,23.917 ; LED19.A@45.039,8.473 LED19.A@45.039,10.807 ; LED19.A@45.039,8.473 LED19.A@45.482,10.764 ; LED19.A@45.039,8.473 LED19.A@45.039,10.807 ; LED19.A@45.039,10.807 44.597,8.516 LED19.A@45.039,10.807 ; LED19.A@45.039,10.807 45.482,8.516 LED19.A@45.039,10.807 ; LED17.A@45.039,21.583 LED17.A@45.039,23.917 ; LED17.A@45.039,21.583 LED17.A@45.457,23.681 ; LED15.A@45.039,34.693 LED15.A@45.039,37.027 ; LED15.A@45.039,34.693 LED15.A@45.482,36.984 ; LED15.A@45.039,34.693 LED15.A@45.039,37.027 ; LED15.A@45.039,37.027 44.597,34.736 LED15.A@45.039,37.027 ; LED15.A@45.039,37.027 45.482,34.736 LED15.A@45.039,37.027 ; LED13.A@45.039,47.803 LED13.A@45.039,50.137 ; LED13.A@45.039,47.803 LED13.A@45.482,50.094 ; LED13.A@45.039,47.803 LED13.A@45.039,50.137 ; LED13.A@45.039,50.137 44.597,47.846 LED13.A@45.039,50.137 ; LED13.A@45.039,50.137 45.482,47.846 LED13.A@45.039,50.137 ; LED11.A@45.039,60.913 LED11.A@45.039,63.247 ; LED11.A@45.039,60.913 LED11.A@45.482,63.204 ; LED11.A@45.039,60.913 LED11.A@45.039,63.247 ; LED11.A@45.039,63.247 44.597,60.956 LED11.A@45.039,63.247 ; LED11.A@45.039,63.247 45.482,60.956 LED11.A@45.039,63.247 ; LED9.A@45.039,74.023 LED9.A@45.039,76.357 ; LED9.A@45.039,74.023 LED9.A@45.482,76.314 ; LED9.A@45.039,74.023 LED9.A@45.039,76.357 ; LED9.A@45.039,76.357 44.597,74.066 LED9.A@45.039,76.357 ; LED9.A@45.039,76.357 45.482,74.066 LED9.A@45.039,76.357 ; LED7.A@45.039,96.813 LED7.A@45.039,99.147 ; LED7.A@45.039,96.813 LED7.A@45.482,99.104 ; LED7.A@45.039,96.813 LED7.A@45.039,99.147 ; LED7.A@45.039,99.147 44.597,96.856 LED7.A@45.039,99.147 ; LED7.A@45.039,99.147 45.482,96.856 LED7.A@45.039,99.147 ; LED5.A@45.039,110.263 LED5.A@45.039,112.597 ; LED5.A@45.039,110.263 LED5.A@45.482,112.554 ; LED5.A@45.039,110.263 LED5.A@45.039,112.597 ; LED5.A@45.039,112.597 44.597,110.306 LED5.A@45.039,112.597 ; LED5.A@45.039,112.597 45.482,110.306 LED5.A@45.039,112.597 ; 46.758,147.217 LED2.A@49.869,147.217 ; 48.88,23.917 LED17.A@52.014,23.722 ; 48.928,10.807 LED19.A@52.039,10.807 ; 48.928,37.027 LED15.A@52.039,37.027 ; 48.928,50.137 LED13.A@52.039,50.137 ; 48.928,63.247 LED11.A@52.039,63.247 ; 48.928,76.357 LED9.A@52.039,76.357 ; 48.928,99.147 LED7.A@52.039,99.147 ; 48.928,112.597 LED5.A@52.039,112.597 ; LED2.A@49.427,147.174 LED2.A@49.869,144.883 ; LED2.A@49.427,147.174 LED2.A@49.869,144.883 ; LED2.A@49.869,144.883 LED2.A@49.869,147.217 ; LED2.A@49.869,144.883 LED2.A@49.869,147.217 ; LED2.A@49.869,147.217 49.427,144.926 LED2.A@49.869,147.217 ; LED2.A@49.869,147.217 50.312,144.926 LED2.A@49.869,147.217 ; LED17.A@51.572,21.432 LED17.A@52.039,23.917 ; LED17.A@51.572,21.432 LED17.A@52.014,23.722 ; LED19.A@51.597,8.516 LED19.A@52.039,10.807 ; LED19.A@51.597,8.516 LED19.A@52.039,10.807 ; LED15.A@51.597,34.736 LED15.A@52.039,37.027 ; LED15.A@51.597,34.736 LED15.A@52.039,37.027 ; LED13.A@51.597,47.846 LED13.A@52.039,50.137 ; LED13.A@51.597,47.846 LED13.A@52.039,50.137 ; LED11.A@51.597,60.956 LED11.A@52.039,63.247 ; LED11.A@51.597,60.956 LED11.A@52.039,63.247 ; LED9.A@51.597,74.066 LED9.A@52.039,76.357 ; LED9.A@51.597,74.066 LED9.A@52.039,76.357 ; LED7.A@51.597,96.856 LED7.A@52.039,99.147 ; LED7.A@51.597,96.856 LED7.A@52.039,99.147 ; LED5.A@51.597,110.306 LED5.A@52.039,112.597 ; LED5.A@51.597,110.306 LED5.A@52.039,112.597 ; LED17.A@52.014,21.389 LED17.A@52.039,23.917 ; LED17.A@52.014,21.389 LED17.A@52.014,23.722 ; LED17.A@52.014,23.722 LED17.A@52.039,21.583 ; LED17.A@52.014,23.722 53.228,23.917 ; LED19.A@52.039,8.473 LED19.A@52.039,10.807 ; LED19.A@52.039,8.473 54.417,8.473 ; LED19.A@52.039,8.473 LED19.A@52.039,10.807 ; LED17.A@52.039,21.583 LED17.A@52.039,23.917 ; LED17.A@52.039,23.917 53.228,23.917 ; LED15.A@52.039,34.693 LED15.A@52.039,37.027 ; LED15.A@52.039,34.693 53.745,34.693 ; LED15.A@52.039,34.693 LED15.A@52.039,37.027 ; LED15.A@52.039,37.027 LED15.A@52.482,34.736 ; LED13.A@52.039,47.803 LED13.A@52.039,50.137 ; LED13.A@52.039,47.803 LED13.A@52.039,50.137 ; LED13.A@52.039,50.137 53.292,50.137 ; LED13.A@52.039,50.137 LED13.A@52.482,47.846 ; LED11.A@52.039,60.913 LED11.A@52.039,63.247 ; LED11.A@52.039,60.913 53.344,60.913 ; LED11.A@52.039,60.913 LED11.A@52.039,63.247 ; LED11.A@52.039,63.247 LED11.A@52.482,60.956 ; LED9.A@52.039,74.023 LED9.A@52.039,76.357 ; LED9.A@52.039,74.023 53.637,74.023 ; LED9.A@52.039,74.023 LED9.A@52.039,76.357 ; LED7.A@52.039,96.813 LED7.A@52.039,99.147 ; LED7.A@52.039,96.813 LED7.A@52.039,99.147 ; LED5.A@52.039,110.263 LED5.A@52.039,112.597 ; LED5.A@52.039,110.263 LED5.A@52.039,112.597 ; LED5.A@52.039,112.597 LED5.A@52.482,110.306 ; 53.228,23.917 53.848,24.536 53.848,34.591 53.745,34.693 ; 53.292,50.137 53.745,49.683 53.745,34.693 ; 53.344,60.913 54.051,61.62 54.051,67.462 ; 53.637,74.023 54.051,73.609 54.051,67.462 ; LED1.A@60.657,147.174 LED1.A@61.099,144.883 ; LED1.A@60.657,147.174 LED1.A@61.099,144.883 ; LED1.A@61.099,144.883 LED1.A@61.099,147.217 ; LED1.A@61.099,144.883 LED1.A@61.542,147.174 ; LED1.A@61.099,144.883 LED1.A@61.099,147.217 ; LED1.A@61.099,147.217 60.657,144.926 LED1.A@61.099,147.217 ; LED1.A@61.099,147.217 61.542,144.926 LED1.A@61.099,147.217
  BottomLayer w1.016: LED20.A@9.601,10.807 LED20.A@9.799,10.807 16.418,10.807 26.26,0.965 50.07,0.965 53.415,4.31 54.559,4.31 62.3,4.31 63.45,5.46 63.45,16.75 ; P1.2@65.724,18.865 63.45,16.75 ; P1.2@66.538,17.083 63.45,16.75 ; C6.1@70.917,28.854 72.695,28.854 ; 63.45,16.75 64.74,18.04 ; 63.45,16.75 P1.2@66.275,18.04 ; 64.74,18.04 P1.2@66.275,18.04 ; 64.74,18.04 65.954,17.101 64.74,18.04 ; 64.74,18.04 65.954,18.979 64.74,18.04 ; 64.74,18.04 P1.2@66.275,18.04 ; 64.74,18.04 P1.2@66.275,18.04 ; P1.2@66.275,18.04 66.275,17.225 68.463,15.037 ; 68.463,15.037 P4.2@70.256,15.037 ; 68.463,15.037 P4.2@70.256,15.037 ; P2.4@69.139,41.808 P3.4@66.548,41.808 P2.4@69.139,41.808 ; P2.4@69.139,41.808 71.984,41.808 72.695,41.097 72.695,28.854 ; P4.2@70.256,15.037 71.475,15.037 ; P4.2@70.256,15.037 72.695,16.257 ; P4.2@70.256,15.037 71.475,15.037 ; 71.475,15.037 72.695,16.257 ; 72.695,16.257 72.695,25.31 72.806,25.421 72.806,28.743 72.695,28.854
VPP1: C4.1 R7.1 U1.9 烧入口1.2 | length 49.7
  TopLayer w0.406: 烧入口1.2@59.964,91.535 60.503,93.015 ; 烧入口1.2@59.978,91.286 60.604,90.119 ; U1.9@60.887,73.373 60.887,75.751 ; U1.9@60.887,74.44 60.887,75.751 ; 烧入口1.2@61.041,91.535 60.503,93.015 ; 烧入口1.2@61.045,91.369 60.604,90.119 ; R7.1@62.997,95.27 63.423,94.004 ; R7.1@63.423,95.34 63.423,94.004 ; R7.1@63.473,95.038 65.277,95.467 R7.1@63.473,95.896 ; R7.1@63.849,95.27 63.423,94.004 ; C4.1@66.116,95.038 64.312,95.467 ; C4.1@66.116,95.896 64.312,95.467 ; 烧入口1.2@60.503,91.44 60.503,93.015 ; 烧入口1.2@60.503,91.44 60.604,91.338 60.604,90.119 ; 烧入口1.2@60.503,91.44 60.604,90.119 ; 60.503,93.015 61.112,93.624 63.043,93.624 63.423,94.004 ; 60.604,90.119 59.862,89.376 59.862,76.776 60.887,75.751 ; 63.423,94.004 R7.1@63.423,95.467 C4.1@66.166,95.467 64.312,95.467
pads on no net: Mini_S1.0 Mini_S2.0 Mini_S3.0 Mini_S4.0 U1.44

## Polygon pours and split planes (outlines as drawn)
GND on TopLayer "Top" (solid, remove dead copper, pour order 5): 0,0 74.95,0 75,0.05 75,152 0,152
GND on BottomLayer "Top" (solid, remove dead copper, pour order 6): 0,0 74.95,0 75,0.05 75,152 0,152

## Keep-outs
KeepOutLayer:
  circle w0.254: c15,120 r2
  circle w0.254: c71.34,138.151 r2
  circle w0.254: c71.401,3.66 r2
  circle w0.254: c55,120 r2
  circle w0.254: c15.251,145.135 r2
  circle w0.254: c15.35,76.35 r2
  circle w0.254: c15.35,3.8 r2
  circle w0.254: c15,120 r3.5
  circle w0.254: c71.34,138.151 r3.5
  circle w0.254: c71.401,3.66 r3.5
  circle w0.254: c55,120 r3.5
  circle w0.254: c15.251,145.135 r3.5
  circle w0.254: c15.35,76.35 r3.5
  circle w0.254: c15.35,3.8 r3.5
  lines w0.127: 0,0 0,152 75,152 75,0 72.542,0 0,0

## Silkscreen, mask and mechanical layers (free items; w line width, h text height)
TopOverlay:
  drawing of 2870 lines, arcs and shapes, not listed
  text "远程控制" at 11.5,137.925 h3
  text "本地控制" at 51.57,137.925 h3
  text "开机" at 4.275,118.9 h3
  text "开机" at 44.345,118.9 h3
  text "值机" at 23.009,118.776 h3
  text "值机" at 63.079,118.776 h3
  text "电源" at 3.6,103.875 h3
  text "值机" at 45.84,103.875 h3
  text "运行" at 3.6,90.425 h3
  text "通讯" at 45.84,90.425 h3
  text "CL-KB-V1.1" at 21.133,75.975 h4
  text "故障" at 3.576,67.635 h3
  text "缺风" at 45.816,67.635 h3
  text "电热高温" at 44.842,54.842 h3
  text "初效" at 3.575,54.625 h3
  text "中效" at 3.576,41.415 h3
  text "预热高温" at 44.842,41.392 h3
  text "亚高" at 3.575,28.405 h3
  text "防冻报警" at 44.842,28.392 h3
  text "高效" at 3.576,15.195 h3
  text "防冻停机" at 44.842,14.992 h3
  text "A+ B- V G" at 73.55,7.725 h3 r90
  text "消防" at 46.55,2.25 h3
  text "急停" at 5.025,2.125 h3
BottomOverlay:
  drawing of 2870 lines, arcs and shapes, not listed
  text "CL-KB-V1.1" at 36.539,75.975 h4
Mechanical1:
  circle w0.254: c15.35,3.8 r2
  circle w0.254: c15.35,76.35 r2
  circle w0.254: c15.251,145.135 r2
  circle w0.254: c55,120 r2
  circle w0.254: c71.401,3.66 r2
  circle w0.254: c71.34,138.151 r2
  circle w0.254: c15,120 r2
  lines w0.127: 0,3.5 ccw(c3.5,3.5) 3.5,0 ; 0,148.5 cw(c3.5,148.5) 3.5,152 ; 71.5,0 ccw(c71.5,3.5) 75,3.5 ; 71.5,152 cw(c71.5,148.5) 75,148.5 ; 0,0 72.542,0 75,0 75,152 0,152 0,0
DrillDrawing:
  text ".legend" at 111.6,82.925 h2.03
